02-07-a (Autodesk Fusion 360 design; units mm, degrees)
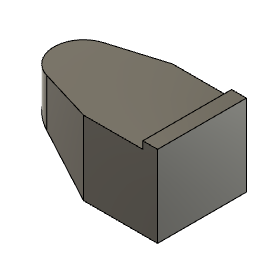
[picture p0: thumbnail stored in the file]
sketch "スケッチ1" plane through (0, 0, 0) normal (0, 0, 1) x axis (1, 0, 0)
  line L1 (-50, 25) -> (50, 25)
  line L2 (-50, -25) -> (-50, 25)
  line L3 (50, -25) -> (-50, -25)
  line L4 (50, 25) -> (50, -25)
  line L5 (-50, -25) -> (50, 25)
  line L6 (50, -25) -> (-50, 25)
  point P6 (0, 0)
  point P1 (0, 0)
  point P2 (50, 25)
  point P3 (-50, 25)
  point P5 (50, -25)
  horizontal L1
  perpendicular L1 L2
  parallel L1 L3
  parallel L2 L4
  coincident L5 P6
  coincident L6 P6
  coincident P1 P6
  dimension "d1" distance P2 P3 = 100
  dimension "d2" distance P2 P5 = 50
extrude "押し出し1" new body sketch "スケッチ1" profile of L1 L2 L3 L4 distance 60
sketch "スケッチ2" plane through (0, 25, 0) normal (0, 1, 0) x axis (-1, 0, 0)
  line L1 (50, 30) -> (50, -30)
  line L2 (-50, 30) -> (50, 30)
  line L3 (-50, -30) -> (-50, 30)
  line L4 (50, -30) -> (-50, -30)
  line L5 (-50, -30) -> (-40, -30)
  line L6 (-50, 30) -> (-50, -30)
  line L7 (-40, 30) -> (-50, 30)
  line L8 (-40, -30) -> (-40, 30)
  point P5 (-50, -30)
  point P7 (-50, -30)
  point P4 (-50, 30)
  point P8 (-50, 30)
  point P6 (-40, -30)
  horizontal L5
  vertical L6
  horizontal L7
  vertical L8
  coincident P5 P7
  coincident P4 P8
  dimension "d5" distance P6 P7 = 10
extrude "押し出し2" add sketch "スケッチ2" profile of L2 L3 L4 L5 L6 L7 L8 along normal blind 5
sketch "スケッチ4" plane through (0, 0, 30) normal (0, 0, 1) x axis (1, 0, 0)
  line L1 (50, 30) -> (50, -25)
  line L2 (40, 30) -> (50, 30)
  line L3 (40, 25) -> (40, 30)
  line L4 (-50, 25) -> (40, 25)
  line L5 (-50, -25) -> (-50, 25)
  line L6 (50, -25) -> (-50, -25)
  line L7 (0, -25) -> (-50, -25)
  line L8 (-50, 0) -> (0, -25)
  line L9 (-50, -25) -> (-50, 0)
  point P8 (-50, -25)
  point P10 (-50, 0)
  point P9 (0, -25)
  parallel L5 L9
  collinear L5 L9
  collinear L6 L7
  dimension "d10" distance P8 P10 = 25
  dimension "d11" distance P8 P9 = 50
extrude "押し出し3" cut sketch "スケッチ4" profile of L5 L6 L7 L8 L9 no distance stored
sketch "スケッチ5" plane through (0, 25, 0) normal (0, 1, 0) x axis (-1, 0, 0)
  line L1 (-40, -30) -> (-40, 30)
  line L2 (50, -30) -> (-40, -30)
  line L3 (50, 30) -> (50, -30)
  line L4 (-40, 30) -> (50, 30)
  line L5 (0, -30) -> (35.8055, -19.1389)
  line L6 (-50, -30) -> (0, -30)
  line L7 (-50, 30) -> (-50, -30)
  line L8 (0, 30) -> (-50, 30)
  line L9 (35.8055, 19.1389) -> (0, 30)
  line L10 (-50, -30) -> (-50, 30)
  arc A1 centre (30, 0) radius 20 clockwise from (35.8055, 19.1389) to (35.8055, -19.1389)
  point P7 (0, -30)
  point P8 (-50, -30)
  horizontal L6
  perpendicular L6 L7
  perpendicular L7 L8
  tangent L5 A1
  tangent L9 A1
  equal L5 L9
  equal L6 L8
  collinear L2 L6
  collinear L4 L8
  collinear L7 L10
  tangent L3 A1
  dimension "d13" distance P7 P8 = 50
  dimension "d14" radius A1 = 20
extrude "押し出し4" sketch "スケッチ5" profile of L1 L2 L4 L5 L6 L7 L8 L9 A1 L10 no distance stored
